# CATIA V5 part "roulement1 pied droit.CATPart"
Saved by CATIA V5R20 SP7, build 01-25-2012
Part number: roulement 1 pied droit
Bounding box of the stored display mesh (mm): x 17.514 to 31.522, y -79 to -65, z -6.556 to 4.707
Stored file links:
  F:\Travaux\Modélisations\CFAO_2011\CFAO_2011_MMS\CFAO_2011_MMS_DONE\CFAO_2011_MMS_jboiteux\Catia\roulement1 pied droit.CATPart
  U:\finthinkmotion\stepper.CATProduct
  F:\Travaux\Modélisations\CFAO_2011\CFAO_2011_MMS\CFAO_2011_MMS_DONE\CFAO_2011_MMS_jboiteux\Catia\rondelle1 pied droit.CATPart
  F:\Travaux\Modélisations\CFAO_2011\CFAO_2011_MMS\CFAO_2011_MMS_DONE\CFAO_2011_MMS_jboiteux\Catia\entretoise pied droit.CATPart
  F:\Travaux\Modélisations\CFAO_2011\CFAO_2011_MMS\CFAO_2011_MMS_DONE\CFAO_2011_MMS_jboiteux\Catia\Part1.CATPart
  F:\Travaux\Modélisations\CFAO_2011\CFAO_2011_MMS\CFAO_2011_MMS_DONE\CFAO_2011_MMS_jboiteux\Catia\bati.CATPart
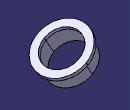
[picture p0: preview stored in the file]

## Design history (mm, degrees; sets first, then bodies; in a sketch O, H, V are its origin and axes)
Parameters
  rayontube = 9 mm {= External.royontubebati}
External parameters (linked from other documents)
  External.royontubebati = 9 mm
Set1
  DatumSurface1: linked copy from another document
  DatumCurve1: linked copy from another document
  Point1: linked copy from another document
  Point2: linked copy from another document
  DatumCurve2: linked copy from another document
Body1 (main body)
  Sketch1 on face of DatumSurface1, origin (7.3878, 0, 12.796), H (0, 1, 0), V (-0.866, 0, 0.5)
    projected circle E1 centre (-72, -21.4454) radius 7 from edge of DatumCurve1
    circle A1 centre (-72, -21.4454) radius 5
    point P1 (-72, -21.4454)
    reference projected point E2 (-72, -21.4454) from Point1
    radius A1 = 5 {= rayontube *5/9}
    coincidence: E2 P1
  Pad1: profile Sketch1, direction (-0.5, 0, -0.866), length 2, opposite side length -1
  Sketch2 on end face of Pad1, origin (6.3878, 0, 11.0639), H (0, -1, 0), V (-0.866, 0, 0.5)
    circle A1 centre (72, -21.4454) radius 6
    point P1 (72, -21.4454)
    reference projected point E1 (72, -21.4454) from Point2
    projected circle E2 centre (72, -21.4454) radius 5 from edge of DatumCurve2
    radius A1 = 6 {= rayontube *5/9+1mm}
    coincidence: E1 P1
  Pad2: profile Sketch2, direction (-0.5, 0, -0.866), length 4.5 {= rayontube /2}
